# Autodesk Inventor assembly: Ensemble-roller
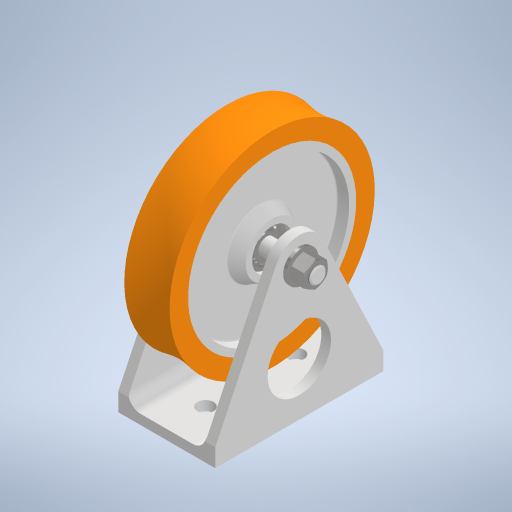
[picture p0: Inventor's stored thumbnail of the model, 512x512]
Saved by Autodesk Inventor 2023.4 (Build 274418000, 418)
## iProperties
Created: 2025-03
Part Number: Ensemble-roller
Document SubType Name: Assembly
Designer: bruno
Author: bruno
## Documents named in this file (8)
- C:\Users\bruno\Documents\1-Cours-2024-25\1STI2D\I2D\4. Pivot\Roller-coaster\Ensemble-roller.iam
- C:\Users\bruno\Documents\Inventor\Content Center Files\R2023\fr-FR\BS 290 SKF(09)\BS 290 SKF - SKF 6305-2Z.ipt
- C:\Users\bruno\Documents\1-Cours-2024-25\1STI2D\I2D\4. Pivot\Roller-coaster\roue.ipt
- C:\Users\bruno\Documents\1-Cours-2024-25\1STI2D\I2D\4. Pivot\Roller-coaster\Bande-roulement.ipt
- C:\Users\bruno\Documents\1-Cours-2024-25\1STI2D\I2D\4. Pivot\Roller-coaster\chape.ipt
- C:\Users\bruno\Documents\Inventor\Content Center Files\R2023\fr-FR\IFI 542(1)\IFI 542 - 24(1).ipt
- C:\Users\bruno\Documents\Inventor\Content Center Files\R2023\fr-FR\AS 1112 (2)\AS 1112 - M24  Type 5.ipt
- C:\Users\bruno\Documents\1-Cours-2024-25\1STI2D\I2D\4. Pivot\Roller-coaster\Vis-hexagonale - M24 x 180.ipt
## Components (8 placed, 7 different names)
1. BS 290 SKF- avec deux flasques Z SKF 6305-2Z:1 — Placage:2, Affleurement:1
2. BS 290 SKF- avec deux flasques Z SKF 6305-2Z:2 — Placage:1, Affleurement:2, Placage:3
3. roue:1 — Logement:1, Placage:1, Placage:2, Affleurement:1, Affleurement:2, Placage:4
4. Bande-roulement:1 — Logement:1
5. chape:1 — Placage:3, Placage:4, Logement:3, Logement:5
6. Rondelle circulaire (Métrique) (IFI) 24:1 — Logement:3, Logement:4
7. AS 1112 (2) - Métrique M24  Type 5:1 — Logement:4
8. Vis-hexagonale - M24 x 180:1 — Logement:5
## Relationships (10: Insert 4, Mate 4, Flush 2)
- Logement:1 [Insert]: roue:1 ↔ Bande-roulement:1
- Placage:1 [Mate]: BS 290 SKF- avec deux flasques Z SKF 6305-2Z:2 ↔ roue:1
- Placage:2 [Mate]: BS 290 SKF- avec deux flasques Z SKF 6305-2Z:1 ↔ roue:1
- Affleurement:1 [Flush]: BS 290 SKF- avec deux flasques Z SKF 6305-2Z:1 ↔ roue:1
- Affleurement:2 [Flush]: BS 290 SKF- avec deux flasques Z SKF 6305-2Z:2 ↔ roue:1
- Placage:3 [Mate]: BS 290 SKF- avec deux flasques Z SKF 6305-2Z:2 ↔ chape:1
- Placage:4 [Mate]: roue:1 ↔ chape:1
- Logement:3 [Insert]: chape:1 ↔ Rondelle circulaire (Métrique) (IFI) 24:1
- Logement:4 [Insert]: Rondelle circulaire (Métrique) (IFI) 24:1 ↔ AS 1112 (2) - Métrique M24  Type 5:1
- Logement:5 [Insert]: chape:1 ↔ Vis-hexagonale - M24 x 180:1
